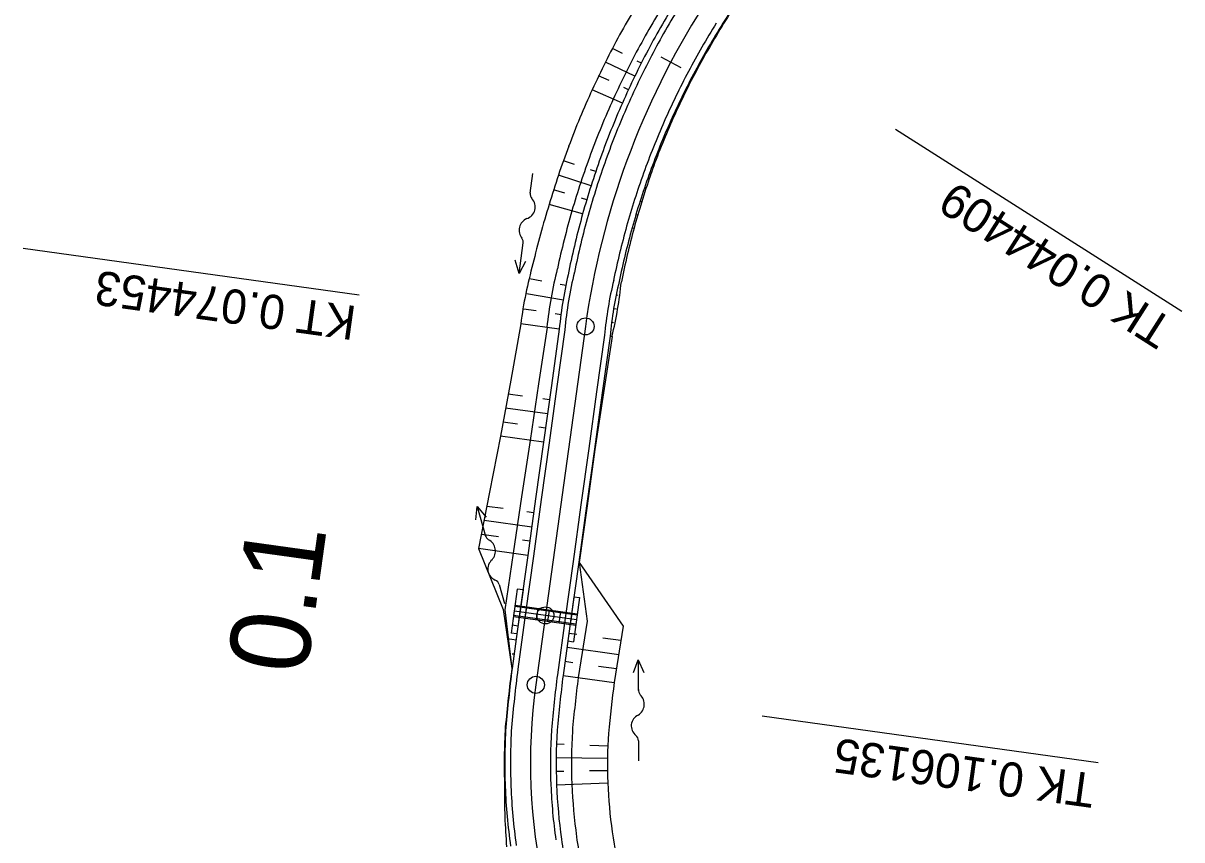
# Model space of a CAD drawing. Extents: x -481656 to -478728, y -1113199 to -1110710.
# Drawn here: x -481656 to -481554.6, y -1112652.7 to -1112581.2 of the extents above; entities that cross this region are included whole.
import ezdxf

# ---------------------------------------------------------------- set-up
doc = ezdxf.new("R2010")
doc.units = 0
for name, color, linetype in [('C11_HATCH_SLOPE_L', 7, 'Continuous'), ('C11_HATCH_SLOPE_R', 7, 'Continuous'), ('C11_HECTOMETRY', 7, 'Continuous'), ('C11_HLBODY', 7, 'Continuous'), ('C11_HRANA_TELESO', 7, 'Continuous'), ('C11_KORUNA', 7, 'Continuous'), ('C11_OSA', 7, 'Continuous'), ('C11_PRIKOP', 7, 'Continuous'), ('C11_STANICENI', 7, 'Continuous'), ('C11_VOZOVKA', 7, 'Continuous'), ('C11_ZPEVKRAJ', 7, 'Continuous'), ('DRENÁŽ', 7, 'Continuous'), ('PLYN', 7, 'Continuous'), ('PROPUSTEK', 7, 'Continuous')]:
    doc.layers.add(name, color=color, linetype=linetype)

# ---------------------------------------------------------------- blocks, each defined once
blk = doc.blocks.new('A$C70B')
at = {"layer": 'DRENÁŽ'}
for p, q in [((0.87, 0), (-0.87, 0)), ((6.86, 0.43), (7.97, 0)), ((7.97, 0), (5.28, 0)), ((7.97, 0), (6.86, -0.48))]:
    blk.add_line(p, q, dxfattribs=at)
for centre, radius, start, end in [((0.87, 0.58), 0.582, 269.6924, 322.7901), ((2.17, -0.42), 1.05, 24.4039, 142.0836), ((4.08, 0.59), 1.11, 210.8873, 317.3707), ((5.32, -0.64), 0.636, 85.9766, 131.7248)]:
    blk.add_arc(centre, radius, start, end, dxfattribs=at)

msp = doc.modelspace()

# ---------------------------------------------------------------- linework, layer by layer
at = {"layer": 'C11_HATCH_SLOPE_L'}
for p, q in [((-481594.92, -1112581.46), (-481594.87, -1112581.5)), ((-481597.9, -1112586.73), (-481597.86, -1112586.75)), ((-481597.82, -1112586.77), (-481597.82, -1112586.77)), ((-481598.43, -1112587.81), (-481598.35, -1112587.85)), ((-481598.95, -1112588.91), (-481598.91, -1112588.93)), ((-481598.86, -1112588.95), (-481598.86, -1112588.95)), ((-481599.45, -1112590.01), (-481599.36, -1112590.05)), ((-481601.64, -1112595.64), (-481601.58, -1112595.67)), ((-481601.51, -1112595.69), (-481601.51, -1112595.69)), ((-481602.02, -1112596.79), (-481601.88, -1112596.84)), ((-481602.38, -1112597.95), (-481602.3, -1112597.97)), ((-481602.23, -1112597.99), (-481602.23, -1112597.99)), ((-481602.71, -1112599.11), (-481602.55, -1112599.16)), ((-481604.08, -1112605), (-481603.99, -1112605.02)), ((-481603.9, -1112605.03), (-481603.9, -1112605.03)), ((-481604.29, -1112606.19), (-481604.11, -1112606.22)), ((-481604.48, -1112607.39), (-481604.39, -1112607.4)), ((-481604.31, -1112607.41), (-481604.31, -1112607.41)), ((-481604.65, -1112608.6), (-481604.48, -1112608.63)), ((-481605.51, -1112614.79), (-481605.46, -1112614.8)), ((-481605.41, -1112614.81), (-481605.41, -1112614.81)), ((-481605.68, -1112616.03), (-481605.59, -1112616.04)), ((-481605.85, -1112617.27), (-481605.82, -1112617.28)), ((-481605.78, -1112617.28), (-481605.78, -1112617.28)), ((-481606.02, -1112618.51), (-481605.97, -1112618.52)), ((-481606.88, -1112624.7), (-481606.86, -1112624.7)), ((-481606.84, -1112624.71), (-481606.84, -1112624.71)), ((-481607.05, -1112625.94), (-481607.01, -1112625.94)), ((-481607.22, -1112627.18), (-481607.2, -1112627.18)), ((-481607.18, -1112627.18), (-481607.18, -1112627.18)), ((-481607.39, -1112628.41), (-481607.36, -1112628.42)), ((-481608.25, -1112634.6), (-481607.55, -1112634.7)), ((-481605.28, -1112635.02), (-481603.7, -1112635.24)), ((-481608.42, -1112635.84), (-481603.89, -1112636.47)), ((-481608.6, -1112637.08), (-481607.92, -1112637.17)), ((-481605.67, -1112637.49), (-481604.09, -1112637.71)), ((-481608.77, -1112638.32), (-481604.29, -1112638.94)), ((-481609.34, -1112644.31), (-481608.67, -1112644.33)), ((-481606.43, -1112644.41), (-481604.85, -1112644.47)), ((-481609.37, -1112645.5), (-481604.88, -1112645.55)), ((-481609.37, -1112646.7), (-481608.7, -1112646.69)), ((-481606.45, -1112646.65), (-481604.88, -1112646.63)), ((-481609.34, -1112647.89), (-481604.85, -1112647.71))]:
    msp.add_line(p, q, dxfattribs=at)
at = {"layer": 'C11_HATCH_SLOPE_R'}
for p, q in [((-481603.55, -1112583.86), (-481604.45, -1112583.41)), ((-481602.48, -1112585.85), (-481605.06, -1112584.6)), ((-481601.91, -1112584.69), (-481602.28, -1112584.51)), ((-481604.73, -1112586.23), (-481605.65, -1112585.81)), ((-481603.57, -1112588.19), (-481606.21, -1112587.02)), ((-481603.04, -1112587.02), (-481603.43, -1112586.83)), ((-481607.76, -1112593.57), (-481608.73, -1112593.24)), ((-481606.31, -1112595.43), (-481609.17, -1112594.52)), ((-481605.9, -1112594.2), (-481606.35, -1112594.05)), ((-481608.6, -1112596.09), (-481609.59, -1112595.79)), ((-481606.69, -1112596.66), (-481607.15, -1112596.52)), ((-481607.05, -1112597.9), (-481609.98, -1112597.08)), ((-481610.61, -1112603.79), (-481611.7, -1112603.59)), ((-481608.5, -1112604.18), (-481609.02, -1112604.09)), ((-481608.73, -1112605.45), (-481611.98, -1112604.91)), ((-481611.11, -1112606.4), (-481612.24, -1112606.23)), ((-481608.93, -1112606.73), (-481609.46, -1112606.65)), ((-481609.11, -1112607.99), (-481612.47, -1112607.52)), ((-481612.33, -1112613.85), (-481613.57, -1112613.68)), ((-481609.97, -1112614.18), (-481610.53, -1112614.1)), ((-481610.14, -1112615.42), (-481613.79, -1112614.91)), ((-481612.74, -1112616.32), (-481614.01, -1112616.14)), ((-481610.31, -1112616.65), (-481610.89, -1112616.57)), ((-481610.48, -1112617.89), (-481614.24, -1112617.37)), ((-481614.01, -1112623.71), (-481615.44, -1112623.51)), ((-481611.51, -1112625.32), (-481615.68, -1112624.74)), ((-481611.34, -1112624.08), (-481611.95, -1112624)), ((-481614.43, -1112626.18), (-481615.92, -1112625.97)), ((-481611.68, -1112626.56), (-481612.31, -1112626.47)), ((-481611.85, -1112627.8), (-481616.16, -1112627.2)), ((-481613.77, -1112633.84), (-481613.82, -1112633.83)), ((-481612.71, -1112633.99), (-481613.21, -1112633.92)), ((-481612.88, -1112635.23), (-481613.63, -1112635.12)), ((-481613.43, -1112636.41), (-481613.44, -1112636.41)), ((-481613.05, -1112636.46), (-481613.23, -1112636.44)), ((-481613.22, -1112637.7), (-481613.26, -1112637.7)), ((-481613.89, -1112644.15), (-481613.89, -1112644.15)), ((-481613.84, -1112644.15), (-481613.86, -1112644.15)), ((-481613.87, -1112645.46), (-481613.92, -1112645.46)), ((-481613.92, -1112646.76), (-481613.92, -1112646.76)), ((-481613.87, -1112646.76), (-481613.89, -1112646.76)), ((-481613.83, -1112648.07), (-481613.88, -1112648.07))]:
    msp.add_line(p, q, dxfattribs=at)
at = {"layer": 'C11_HECTOMETRY'}
msp.add_circle((-481610.31, -1112633.06), 0.75, dxfattribs=at)
at = {"layer": 'C11_HLBODY'}
for p, q in [((-481554.59, -1112606.46), (-481579.65, -1112590.51)), ((-481626.61, -1112605.01), (-481656.03, -1112600.93)), ((-481561.92, -1112645.96), (-481591.34, -1112641.88))]:
    msp.add_line(p, q, dxfattribs=at)
for centre in [(-481606.8, -1112607.75), (-481611.15, -1112639.14)]:
    msp.add_circle(centre, 0.75, dxfattribs=at)
at = {"layer": 'C11_HRANA_TELESO'}
for p, q in [((-481612.47, -1112607.52), (-481613.34, -1112612.45)), ((-481604.48, -1112608.63), (-481605.22, -1112613.57)), ((-481613.34, -1112612.45), (-481614.24, -1112617.37)), ((-481605.22, -1112613.57), (-481605.97, -1112618.52)), ((-481614.24, -1112617.37), (-481615.2, -1112622.28)), ((-481605.97, -1112618.52), (-481606.66, -1112623.47)), ((-481615.2, -1112622.28), (-481616.16, -1112627.2)), ((-481606.66, -1112623.47), (-481607.36, -1112628.42)), ((-481616.16, -1112627.2), (-481614.01, -1112632.55)), ((-481607.36, -1112628.42), (-481603.5, -1112634)), ((-481614.01, -1112632.55), (-481613.26, -1112637.7)), ((-481603.5, -1112634), (-481604.29, -1112638.94))]:
    msp.add_line(p, q, dxfattribs=at)
for centre, radius, start, end in [((-481421.87, -1112687.79), 203.05, 147.0267, 148.4322), ((-481538.33, -1112618.82), 75.02, 146.7075, 150.8011), ((-481537.86, -1112618.17), 75.11, 151.4122, 155.505), ((-481537.35, -1112617.15), 67.67, 148.2076, 152.3001), ((-481537.37, -1112617.16), 67.66, 152.2813, 156.3739), ((-481537.85, -1112618.3), 75.18, 155.4194, 159.5123), ((-481537.34, -1112617.03), 67.64, 156.4907, 160.5833), ((-481537.81, -1112618.42), 75.26, 159.4297, 163.5227), ((-481537.29, -1112616.8), 67.6, 160.7759, 164.8686), ((-481538.03, -1112619.55), 75.38, 162.6591, 166.7535), ((-481537.4, -1112617.09), 67.57, 164.6097, 168.7023), ((-481575.06, -1112612.42), 37.73, 164.4045, 172.5431), ((-481637.28, -1112600.54), 33.78, 346.1579, 354.3818), ((-481457.62, -1112657.52), 156.89, 172.7414, 174.6316), ((-481475.65, -1112655.91), 129.75, 172.4852, 174.4619), ((-481561.62, -1112646.03), 52.3, 176.5048, 182.2344), ((-481561.62, -1112646.09), 43.26, 176.4138, 182.1434), ((-481561.44, -1112648.95), 52.45, 179.0426, 184.7813), ((-481561.63, -1112645.92), 43.26, 182.3665, 188.0961), ((-481561.52, -1112646.54), 43.28, 187.2643, 192.9943)]:
    msp.add_arc(centre, radius, start, end, dxfattribs=at)
at = {"layer": 'C11_KORUNA'}
for p, q in [((-481609.11, -1112607.99), (-481609.79, -1112612.94)), ((-481604.65, -1112608.6), (-481605.34, -1112613.56)), ((-481609.79, -1112612.94), (-481610.48, -1112617.89)), ((-481605.34, -1112613.56), (-481606.02, -1112618.51)), ((-481610.48, -1112617.89), (-481611.17, -1112622.84)), ((-481606.02, -1112618.51), (-481606.71, -1112623.46)), ((-481611.17, -1112622.84), (-481611.85, -1112627.8)), ((-481606.71, -1112623.46), (-481607.39, -1112628.41)), ((-481611.85, -1112627.8), (-481612.54, -1112632.75)), ((-481607.39, -1112628.41), (-481608.08, -1112633.37)), ((-481612.54, -1112632.75), (-481613.22, -1112637.7)), ((-481608.08, -1112633.37), (-481608.77, -1112638.32))]:
    msp.add_line(p, q, dxfattribs=at)
for centre, radius, start, end in [((-481422.09, -1112688.41), 203.25, 146.8481, 148.2523), ((-481537.47, -1112617.36), 72.25, 148.0062, 152.0987), ((-481537.47, -1112617.36), 67.75, 148.0062, 152.0987), ((-481537.47, -1112617.36), 72.25, 152.0987, 156.1913), ((-481537.47, -1112617.36), 67.75, 152.0987, 156.1913), ((-481537.47, -1112617.36), 72.25, 156.1913, 160.2839), ((-481537.47, -1112617.36), 67.75, 156.1913, 160.2839), ((-481537.47, -1112617.36), 72.25, 160.2839, 164.3764), ((-481537.47, -1112617.36), 67.75, 160.2839, 164.3764), ((-481537.47, -1112617.36), 72.25, 164.3764, 168.469), ((-481537.47, -1112617.36), 67.75, 164.3764, 168.469), ((-481573.14, -1112611.41), 36.12, 166.4039, 174.5664), ((-481570.92, -1112611.79), 33.88, 166.3865, 174.6067), ((-481457.68, -1112657.09), 156.75, 172.8965, 174.7871), ((-481466.63, -1112656.17), 143.25, 172.8419, 174.7717), ((-481561.62, -1112646), 52.25, 176.542, 182.2716), ((-481561.62, -1112646), 47.75, 176.542, 182.2716), ((-481561.62, -1112646), 52.25, 182.2716, 188.0012), ((-481561.62, -1112646), 47.75, 182.2716, 188.0012), ((-481561.62, -1112646), 47.75, 188.0012, 193.7307)]:
    msp.add_arc(centre, radius, start, end, dxfattribs=at)
at = {"layer": 'C11_OSA'}
msp.add_line((-481606.8, -1112607.75), (-481611.15, -1112639.14), dxfattribs=at)
for centre, radius, start, end in [((-481537.47, -1112617.36), 70, 147.5225, 172.1135), ((-481561.62, -1112646), 50, 172.1135, 212.884)]:
    msp.add_arc(centre, radius, start, end, dxfattribs=at)
at = {"layer": 'C11_PRIKOP'}
for p, q in [((-481610.17, -1112607.84), (-481610.91, -1112612.78)), ((-481610.91, -1112612.78), (-481611.65, -1112617.73)), ((-481611.65, -1112617.73), (-481612.39, -1112622.68)), ((-481612.39, -1112622.68), (-481613.12, -1112627.62)), ((-481613.12, -1112627.62), (-481613.87, -1112632.56)), ((-481607.36, -1112628.42), (-481606.66, -1112633.56)), ((-481613.87, -1112632.56), (-481613.26, -1112637.7)), ((-481606.66, -1112633.56), (-481607.44, -1112638.5))]:
    msp.add_line(p, q, dxfattribs=at)
for centre, radius, start, end in [((-481537.83, -1112617.98), 73.04, 147.4396, 151.5324), ((-481537.78, -1112618.01), 73.1, 151.5328, 155.6255), ((-481537.74, -1112618.03), 73.15, 155.6254, 159.7181), ((-481537.69, -1112618.04), 73.2, 159.7188, 163.8116), ((-481537.64, -1112618.06), 73.25, 163.8113, 167.9041), ((-481573.74, -1112611.67), 36.64, 165.8389, 173.9919), ((-481469.3, -1112655.87), 139.23, 172.8345, 174.7773), ((-481561.62, -1112645.98), 46.41, 176.5597, 182.2893), ((-481561.62, -1112645.98), 46.41, 182.2891, 188.0187), ((-481561.63, -1112645.98), 46.41, 188.0187, 193.7482)]:
    msp.add_arc(centre, radius, start, end, dxfattribs=at)
at = {"layer": 'C11_STANICENI'}
msp.add_line((-481600.21, -1112584.13), (-481598.45, -1112585.07), dxfattribs=at)
at = {"layer": 'C11_VOZOVKA'}
for p, q in [((-481608.61, -1112608.05), (-481609.3, -1112613.01)), ((-481605.15, -1112608.53), (-481605.83, -1112613.49)), ((-481609.3, -1112613.01), (-481609.98, -1112617.96)), ((-481605.83, -1112613.49), (-481606.52, -1112618.44)), ((-481609.98, -1112617.96), (-481610.67, -1112622.91)), ((-481606.52, -1112618.44), (-481607.2, -1112623.39)), ((-481610.67, -1112622.91), (-481611.36, -1112627.86)), ((-481607.2, -1112623.39), (-481607.89, -1112628.35)), ((-481611.36, -1112627.86), (-481612.04, -1112632.82)), ((-481607.89, -1112628.35), (-481608.58, -1112633.3)), ((-481612.04, -1112632.82), (-481612.73, -1112637.77)), ((-481608.58, -1112633.3), (-481609.26, -1112638.25))]:
    msp.add_line(p, q, dxfattribs=at)
for centre, radius, start, end in [((-481537.47, -1112617.36), 71.75, 148.0062, 152.0987), ((-481537.47, -1112617.36), 68.25, 148.0062, 152.0987), ((-481537.47, -1112617.36), 71.75, 152.0987, 156.1913), ((-481537.47, -1112617.36), 68.25, 152.0987, 156.1913), ((-481537.47, -1112617.36), 71.75, 156.1913, 160.2839), ((-481537.47, -1112617.36), 68.25, 156.1913, 160.2839), ((-481537.47, -1112617.36), 71.75, 160.2839, 164.3764), ((-481537.47, -1112617.36), 68.25, 160.2839, 164.3764), ((-481537.47, -1112617.36), 71.75, 164.3764, 168.469), ((-481537.47, -1112617.36), 68.25, 164.3764, 168.469), ((-481572.9, -1112611.45), 35.88, 166.4021, 174.5707), ((-481571.17, -1112611.74), 34.12, 166.3885, 174.602), ((-481458.67, -1112656.98), 155.25, 172.8908, 174.7855), ((-481465.64, -1112656.27), 144.75, 172.8484, 174.7734), ((-481561.62, -1112646), 51.75, 176.542, 182.2716), ((-481561.62, -1112646), 48.25, 176.542, 182.2716), ((-481561.62, -1112646), 51.75, 182.2716, 188.0012), ((-481561.62, -1112646), 48.25, 182.2716, 188.0012)]:
    msp.add_arc(centre, radius, start, end, dxfattribs=at)
at = {"layer": 'C11_ZPEVKRAJ'}
for p, q in [((-481608.61, -1112608.05), (-481609.3, -1112613.01)), ((-481605.15, -1112608.53), (-481605.83, -1112613.49)), ((-481609.3, -1112613.01), (-481609.98, -1112617.96)), ((-481605.83, -1112613.49), (-481606.52, -1112618.44)), ((-481609.98, -1112617.96), (-481610.67, -1112622.91)), ((-481606.52, -1112618.44), (-481607.2, -1112623.39)), ((-481610.67, -1112622.91), (-481611.36, -1112627.86)), ((-481607.2, -1112623.39), (-481607.89, -1112628.35)), ((-481611.36, -1112627.86), (-481612.04, -1112632.82)), ((-481607.89, -1112628.35), (-481608.58, -1112633.3)), ((-481612.04, -1112632.82), (-481612.73, -1112637.77)), ((-481608.58, -1112633.3), (-481609.26, -1112638.25))]:
    msp.add_line(p, q, dxfattribs=at)
for centre, radius, start, end in [((-481537.47, -1112617.36), 71.75, 148.0062, 152.0987), ((-481537.47, -1112617.36), 68.25, 148.0062, 152.0987), ((-481537.47, -1112617.36), 71.75, 152.0987, 156.1913), ((-481537.47, -1112617.36), 68.25, 152.0987, 156.1913), ((-481537.47, -1112617.36), 71.75, 156.1913, 160.2839), ((-481537.47, -1112617.36), 68.25, 156.1913, 160.2839), ((-481537.47, -1112617.36), 71.75, 160.2839, 164.3764), ((-481537.47, -1112617.36), 68.25, 160.2839, 164.3764), ((-481537.47, -1112617.36), 71.75, 164.3764, 168.469), ((-481537.47, -1112617.36), 68.25, 164.3764, 168.469), ((-481572.9, -1112611.45), 35.88, 166.4021, 174.5707), ((-481571.17, -1112611.74), 34.12, 166.3885, 174.602), ((-481458.67, -1112656.98), 155.25, 172.8908, 174.7855), ((-481465.64, -1112656.27), 144.75, 172.8484, 174.7734), ((-481561.62, -1112646), 51.75, 176.542, 182.2716), ((-481561.62, -1112646), 48.25, 176.542, 182.2716), ((-481561.62, -1112646), 51.75, 182.2716, 188.0012), ((-481561.62, -1112646), 48.25, 182.2716, 188.0012)]:
    msp.add_arc(centre, radius, start, end, dxfattribs=at)
at = {"layer": 'PROPUSTEK'}
for p, q in [((-481612.77, -1112630.75), (-481613.3, -1112634.61)), ((-481612.27, -1112630.82), (-481612.8, -1112634.68)), ((-481612.27, -1112630.82), (-481612.77, -1112630.75)), ((-481607.81, -1112631.44), (-481608.35, -1112635.3)), ((-481607.32, -1112631.5), (-481607.85, -1112635.37)), ((-481607.81, -1112631.44), (-481607.32, -1112631.5)), ((-481612.98, -1112632.28), (-481613.09, -1112633.08)), ((-481607.64, -1112633.83), (-481613.09, -1112633.08)), ((-481607.59, -1112633.44), (-481613.03, -1112632.68)), ((-481607.53, -1112633.04), (-481612.98, -1112632.28)), ((-481607.52, -1112632.94), (-481612.96, -1112632.19)), ((-481611.97, -1112632.32), (-481612.11, -1112633.31)), ((-481610.98, -1112632.46), (-481611.12, -1112633.45)), ((-481609.99, -1112632.6), (-481610.13, -1112633.59)), ((-481609, -1112632.73), (-481609.14, -1112633.73)), ((-481608.01, -1112632.87), (-481608.15, -1112633.86)), ((-481607.65, -1112633.93), (-481613.1, -1112633.18)), ((-481612.8, -1112634.68), (-481613.3, -1112634.61)), ((-481608.35, -1112635.3), (-481607.85, -1112635.37))]:
    msp.add_line(p, q, dxfattribs=at)

# ---------------------------------------------------------------- block references
at = {"layer": 'PLYN'}
for p, rotation in [((-481611.53, -1112595.21), -97.86484546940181), ((-481614.12, -1112631.19), 105.67364725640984), ((-481602.16, -1112644.91), 90.17659526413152)]:
    msp.add_blockref('A$C70B', p, dxfattribs=dict(at, rotation=rotation))

# ---------------------------------------------------------------- texts
at = {"layer": 'C11_HECTOMETRY'}
msp.add_text('0.1', height=7, rotation=82.0679, dxfattribs=at).set_placement((-481631.25, -1112638.4))
at = {"layer": 'C11_HLBODY'}
for s, height, rotation, p in [('TK 0.044409', 2.999, 147.5225, (-481555.13, -1112607.3)), ('KT 0.074453', 3, 172.1135, (-481626.75, -1112606)), ('TK 0.106135', 3, 172.1135, (-481562.06, -1112646.95))]:
    msp.add_text(s, height=height, rotation=rotation, dxfattribs=at).set_placement(p)

doc.saveas('drawing.dxf')
